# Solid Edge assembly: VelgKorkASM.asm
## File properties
Author: KULL
Template: Iso Metric Assembly.asm
Last saved by: KULL
Revision: 6
Application: Solid Edge
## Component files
Velg2.par
VeljekorkASM.asm
Rehv1.par
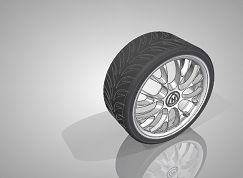
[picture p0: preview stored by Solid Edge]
